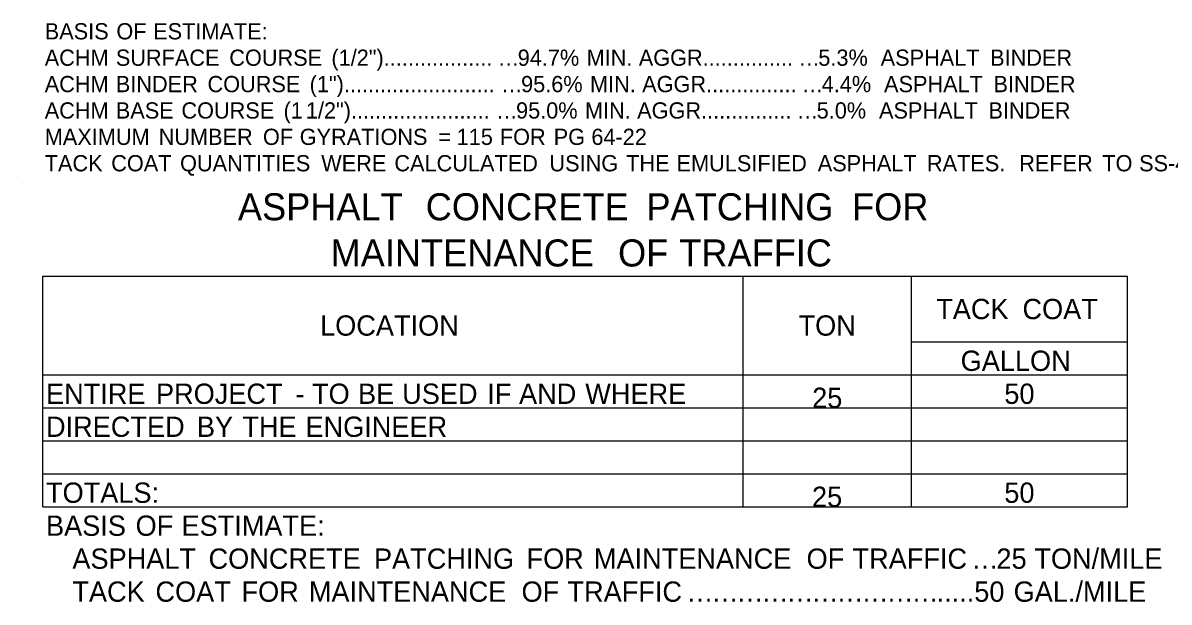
# Model space of a CAD drawing. Extents: x 977434 to 989596, y 1525697 to 1528336.
# Drawn here: x 982699.1 to 983038, y 1527437.3 to 1527608.5 of the extents above; entities that cross this region are included whole.
import ezdxf

# ---------------------------------------------------------------- set-up
doc = ezdxf.new("R2010")
doc.units = 0
doc.layers.add('Default', color=7, linetype='Continuous')
doc.layers.add('R_Border Prem', color=7, linetype='Continuous')

msp = doc.modelspace()

# ---------------------------------------------------------------- linework, layer by layer
at = {"layer": 'Default'}
for p, q in [((982704.92, 1527533.65), (983025.7, 1527533.65)), ((982704.92, 1527465.4), (982704.92, 1527533.65)), ((982704.92, 1527465.4), (982704.92, 1527533.65)), ((982912.11, 1527465.4), (982912.11, 1527533.65)), ((982961.83, 1527465.4), (982961.83, 1527533.65)), ((983025.7, 1527465.4), (983025.7, 1527533.65)), ((983025.7, 1527514.15), (983025.7, 1527533.65)), ((982961.83, 1527514.15), (983025.7, 1527514.15)), ((982961.83, 1527465.4), (982961.83, 1527514.15)), ((982704.92, 1527504.4), (983025.7, 1527504.4)), ((982912.11, 1527465.4), (982912.11, 1527504.4)), ((983025.7, 1527484.9), (983025.7, 1527504.4)), ((982704.92, 1527494.65), (983025.7, 1527494.65)), ((982704.92, 1527484.9), (983025.7, 1527484.9)), ((982704.92, 1527475.15), (983025.7, 1527475.15)), ((983025.7, 1527465.4), (983025.7, 1527475.15)), ((982704.92, 1527465.4), (983025.7, 1527465.4))]:
    msp.add_line(p, q, dxfattribs=at)
at = {"layer": 'R_Border Prem'}
msp.add_line((982699.07, 1527560.95), (982699.07, 1527560.95), dxfattribs=at)

# ---------------------------------------------------------------- texts
at = {"layer": 'Default'}
for s, height, p in [('BASIS', 4.8, (982705.52, 1527603.6)), (' OF', 4.8, (982724.93, 1527603.6)), (' ESTIMATE:', 4.8, (982735.8, 1527603.6)), ('ACHM', 4.8, (982705.52, 1527595.8)), (' SURFACE', 4.8, (982724.76, 1527595.8)), (' COURSE', 4.8, (982758.32, 1527595.8)), (' (1/2")..................', 4.8, (982788.52, 1527595.8)), ('94.7%', 4.8, (982845.4, 1527595.8)), (' MIN.', 4.8, (982863.99, 1527595.8)), (' AGGR...............', 4.8, (982879.42, 1527595.8)), ('5.3%', 4.8, (982934.31, 1527595.8)), ('  ASPHALT', 4.8, (982949.17, 1527595.8)), (' BINDER', 4.8, (982983.33, 1527595.8)), ('…', 4.8, (982839.48, 1527595.8)), ('…', 4.8, (982928.39, 1527595.8)), ('ACHM', 4.8, (982705.52, 1527588)), (' BINDER', 4.8, (982724.76, 1527588)), (' COURSE', 4.8, (982751.88, 1527588)), (' (1").........................', 4.8, (982782.08, 1527588)), ('95.6%', 4.8, (982846.4, 1527588)), (' MIN.', 4.8, (982865, 1527588)), (' AGGR...............', 4.8, (982880.43, 1527588)), ('4.4%', 4.8, (982935.31, 1527588)), ('  ASPHALT', 4.8, (982950.17, 1527588)), (' BINDER', 4.8, (982984.33, 1527588)), ('…', 4.8, (982840.48, 1527588)), ('…', 4.8, (982929.39, 1527588)), ('ACHM', 4.8, (982705.52, 1527580.2)), (' BASE', 4.8, (982724.76, 1527580.2)), (' COURSE', 4.8, (982744.16, 1527580.2)), (' (1', 4.8, (982774.37, 1527580.2)), (' 1/2").......................', 4.8, (982780.96, 1527580.2)), ('95.0%', 4.8, (982844.91, 1527580.2)), (' MIN.', 4.8, (982863.51, 1527580.2)), (' AGGR...............', 4.8, (982878.94, 1527580.2)), ('5.0%', 4.8, (982933.82, 1527580.2)), ('  ASPHALT', 4.8, (982948.68, 1527580.2)), (' BINDER', 4.8, (982982.84, 1527580.2)), ('…', 4.8, (982838.99, 1527580.2)), ('…', 4.8, (982927.9, 1527580.2)), ('MAXIMUM', 4.8, (982705.52, 1527572.4)), (' NUMBER', 4.8, (982737.43, 1527572.4)), (' OF', 4.8, (982768.27, 1527572.4)), (' GYRATIONS', 4.8, (982779.14, 1527572.4)), (' =', 4.8, (982820.15, 1527572.4)), (' 115', 4.8, (982825.56, 1527572.4)), (' FOR', 4.8, (982838.34, 1527572.4)), (' PG', 4.8, (982854.26, 1527572.4)), (' 64-22', 4.8, (982865.4, 1527572.4)), ('TACK', 4.8, (982705.52, 1527564.6)), (' COAT', 4.8, (982723.4, 1527564.6)), (' QUANTITIES', 4.8, (982743.76, 1527564.6)), (' WERE', 4.8, (982785.51, 1527564.6)), (' CALCULATED', 4.8, (982807.14, 1527564.6)), (' USING', 4.8, (982853, 1527564.6)), (' THE', 4.8, (982875.68, 1527564.6)), (' EMULSIFIED', 4.8, (982890.6, 1527564.6)), (' ASPHALT', 4.8, (982932.35, 1527564.6)), (' RATES.', 4.8, (982964.64, 1527564.6)), ('  REFER', 4.8, (982990.15, 1527564.6)), (' TO', 4.8, (983016.51, 1527564.6)), (' SS-400-1', 4.8, (983027.39, 1527564.6)), ('ASPHALT', 8, (982762.66, 1527550.12)), (' CONCRETE', 8, (982815.22, 1527550.12)), (' PATCHING', 8, (982880.5, 1527550.12)), (' FOR', 8, (982941.31, 1527550.12)), ('MAINTENANCE', 8, (982790.06, 1527536.47)), (' OF', 8, (982872.1, 1527536.47)), (' TRAFFIC', 8, (982890.21, 1527536.47)), ('TACK', 6, (982969.18, 1527520.9)), (' COAT', 6, (982992.45, 1527520.9)), ('LOCATION', 6, (982786.96, 1527516.02)), ('TON', 6, (982928.46, 1527516.02)), ('GALLON', 6, (982976.4, 1527505.6)), ('ENTIRE', 6, (982705.9, 1527495.85)), (' PROJECT', 6, (982736.19, 1527495.85)), (' TO', 6, (982782.34, 1527495.85)), (' BE', 6, (982795.94, 1527495.85)), (' USED', 6, (982809, 1527495.85)), (' IF', 6, (982834.18, 1527495.85)), (' AND', 6, (982843.57, 1527495.85)), (' WHERE', 6, (982863.15, 1527495.85)), ('50', 6, (982989.31, 1527495.85)), (' -', 6, (982777.48, 1527495.85)), ('25', 6, (982932.48, 1527494.65)), ('DIRECTED', 6, (982705.9, 1527486.1)), (' BY', 6, (982748.3, 1527486.1)), (' THE', 6, (982761.75, 1527486.1)), (' ENGINEER', 6, (982780.4, 1527486.1)), ('TOTALS:', 6, (982705.9, 1527466.6)), ('25', 6, (982932.44, 1527465.4)), ('50', 6, (982989.31, 1527466.6)), ('BASIS', 6, (982705.9, 1527456.85)), (' OF', 6, (982730.16, 1527456.85)), (' ESTIMATE:', 6, (982743.74, 1527456.85)), (' TON/MILE', 6, (982995.97, 1527447.1)), ('ASPHALT', 6, (982713.7, 1527447.1)), (' CONCRETE', 6, (982751.74, 1527447.1)), (' PATCHING', 6, (982800.66, 1527447.1)), (' FOR', 6, (982845.79, 1527447.1)), (' MAINTENANCE', 6, (982865.7, 1527447.1)), (' OF', 6, (982928.6, 1527447.1)), (' TRAFFIC', 6, (982942.19, 1527447.1)), ('25', 6, (982986.98, 1527447.1)), ('…', 6, (982979.58, 1527447.1)), ('TACK', 6, (982713.7, 1527437.35)), (' COAT', 6, (982736.04, 1527437.35)), (' FOR', 6, (982761.49, 1527437.35)), (' MAINTENANCE', 6, (982781.4, 1527437.35)), (' OF', 6, (982844.31, 1527437.35)), (' TRAFFIC', 6, (982857.89, 1527437.35)), ('.....50', 6, (982969.28, 1527437.35)), (' GAL./MILE', 6, (982989.83, 1527437.35)), ('…', 6, (982895.28, 1527437.35)), ('…', 6, (982902.68, 1527437.35)), ('…', 6, (982910.08, 1527437.35)), ('…', 6, (982917.48, 1527437.35)), ('…', 6, (982924.88, 1527437.35)), ('…', 6, (982932.28, 1527437.35)), ('…', 6, (982939.68, 1527437.35)), ('…', 6, (982947.08, 1527437.35)), ('…', 6, (982954.48, 1527437.35)), ('…', 6, (982961.88, 1527437.35))]:
    msp.add_text(s, height=height, dxfattribs=at).set_placement(p)

doc.saveas('drawing.dxf')
